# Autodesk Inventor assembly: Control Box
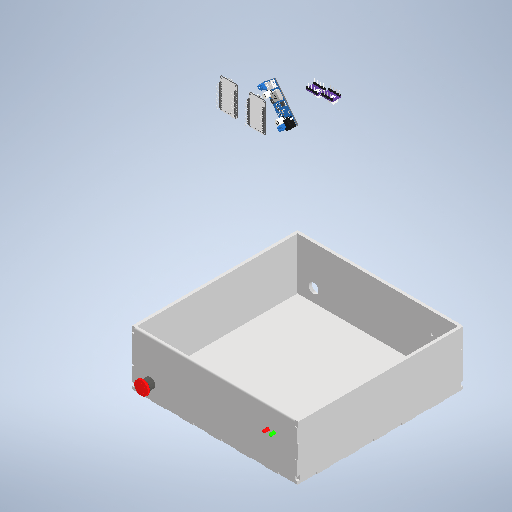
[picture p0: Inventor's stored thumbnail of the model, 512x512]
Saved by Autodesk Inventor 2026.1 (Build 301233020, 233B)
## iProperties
Created: 2026-11
Part Number: Control Box
Document SubType Name: Assembly
Designer: hp
Author: hp
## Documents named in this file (12)
- C:\Users\hp\Documents\Inventor\DOM1_CartesianRobot\Control Box.iam
- C:\Users\hp\Documents\Inventor\DOM1_CartesianRobot\Bottom of Control Box.ipt
- C:\Users\hp\Documents\Inventor\DOM1_CartesianRobot\Right of Control Box.ipt
- C:\Users\hp\Documents\Inventor\DOM1_CartesianRobot\Left of Control Box.ipt
- C:\Users\hp\Documents\Inventor\DOM1_CartesianRobot\Front of Control Box.ipt
- C:\Users\hp\Documents\Inventor\DOM1_CartesianRobot\Back of Control Box.ipt
- C:\Users\hp\Documents\Inventor\DOM1_CartesianRobot\STEP_LED_DIODE_5mm.ipt
- C:\Users\hp\Documents\Inventor\DOM1_CartesianRobot\Emergency stop switch_AB6-A.ipt
- C:\Users\hp\Documents\Inventor\DOM1_CartesianRobot\ESP-32.ipt
- C:\Users\hp\Documents\Inventor\DOM1_CartesianRobot\DRV8825_pin_heatsink.ipt
- C:\Users\hp\Documents\Inventor\DOM1_CartesianRobot\L298N Motor Driver.iam
- C:\Users\hp\Documents\Inventor\DOM1_CartesianRobot\Buck_XY3606.ipt
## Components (14 placed, 11 different names)
1. Bottom of Control Box:1
2. Right of Control Box:1
3. Left of Control Box:1 — Mate:1, Flush:1, Mate:2, Flush:4
4. Front of Control Box:1 — Mate:5, Flush:3, Flush:4
5. Back of Control Box:1 — Mate:6, Flush:5, Mate:7
6. STEP_LED_DIODE_5mm:1 — Mate:8, Mate:10
7. STEP_LED_DIODE_5mm:2 — Mate:9, Mate:11
8. Emergency stop switch_AB6-A:1 — Mate:12, Mate:13
9. ESP-32:1
10. ESP-32:2
11. DRV8825_pin_heatsink:1
12. DRV8825_pin_heatsink:2
13. L298N Motor Driver:1 [sub-assembly]
14. Buck_XY3606:1
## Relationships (15: Mate 11, Flush 4)
- Mate:1: Left of Control Box:1
- Flush:1: Left of Control Box:1
- Mate:2: Left of Control Box:1
- Mate:5: Front of Control Box:1
- Flush:3: Front of Control Box:1
- Flush:4: Left of Control Box:1 ↔ Front of Control Box:1
- Mate:6: Back of Control Box:1
- Flush:5: Back of Control Box:1
- Mate:7: Back of Control Box:1
- Mate:8: STEP_LED_DIODE_5mm:1
- Mate:9: STEP_LED_DIODE_5mm:2
- Mate:10: STEP_LED_DIODE_5mm:1
- Mate:11: STEP_LED_DIODE_5mm:2
- Mate:12: Emergency stop switch_AB6-A:1
- Mate:13: Emergency stop switch_AB6-A:1
